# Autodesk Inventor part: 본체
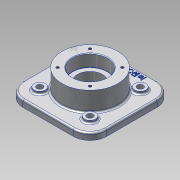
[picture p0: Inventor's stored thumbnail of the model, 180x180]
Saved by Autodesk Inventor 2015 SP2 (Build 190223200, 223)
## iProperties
Created: 2015-07
Part Number: 본체
Material: 일반
Document SubType Name: Modeling
Designer: AMC
Density: 1 g/cm^3
Appearance: 알루미늄 - 평지
Author: AMC
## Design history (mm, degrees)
sketch "스케치1"
  geometry: L1 (-75, -75)-(75, -75); L2 (75, -75)-(75, 75); L3 (75, 75)-(-75, 75); L4 (-75, 75)-(-75, -75); L5 (-75, -75)-(75, 75); L6 (75, -75)-(-75, 75); 1 further point
  constraints: 12 end point, 2 midpoint, 2 parallel, 1 horizontal, 1 perpendicular
  dimensions: "d0" = 150 distance of L3.end L2.end; "d1" = 150 distance of L2.end L1.end
extrude "돌출1" new body sketch "스케치1" distance "d2" = 12; taper "d3" = 0 deg
sketch "스케치2"
  geometry: C1 r 50 at (0, 0); 1 further point
  constraints: 1 centre point, 1 coincident
  dimensions: "d4" = 100 diameter of C1
extrude "돌출2" join sketch "스케치2" distance "d5" = 47; taper "d7" = 0 deg; dims "d6" = 23, "d8" = 0
fillet "모깎기1" dims "d9" = 30
hole "구멍1" diameter "d12" = 45; stored, may be unused: countersink angle "d16" = 90 deg, drill point angle "d18" = 0 deg; dims "d10" = 10, "d11" = 10, "d13" = 6, "d14" = 62, "d15" = 22, "d17" = 8
hole "구멍2" diameter "d21" = 62; stored, may be unused: countersink angle "d25" = 90 deg, drill point angle "d27" = 0 deg; dims "d19" = 10, "d20" = 10, "d22" = 6, "d23" = 62, "d24" = 22, "d26" = 22
sketch "스케치3"
  geometry: C1 r 10 at (-45, 45); C2 r 10 at (45, 45); C3 r 10 at (45, -45); C4 r 10 at (-45, -45); A1 r 30 centre (-45, 45) between (-45, 75) and (-75, 45) reference; A2 r 30 centre (45, 45) between (75, 45) and (45, 75) reference; A3 r 30 centre (45, -45) between (45, -75) and (75, -45) reference; A4 r 30 centre (-45, -45) between (-75, -45) and (-45, -75) reference; 1 further point
  constraints: 4 centre point, 4 coincident
  dimensions: "d28" = 20 diameter of C1; "d29" = 20 diameter of C2; "d30" = 20 diameter of C3; "d31" = 20 diameter of C4
extrude "돌출3" join sketch "스케치3" distance "d32" = 5; taper "d33" = 0 deg
hole "구멍3" diameter "d36" = 11; stored, may be unused: countersink angle "d40" = 90 deg, drill point angle "d42" = 0 deg; dims "d34" = 10, "d35" = 10, "d37" = 6, "d38" = 62, "d39" = 22, "d41" = 22
hole "구멍4" diameter "d45" = 11; stored, may be unused: countersink angle "d49" = 90 deg, drill point angle "d51" = 0 deg; dims "d43" = 10, "d44" = 10, "d46" = 6, "d47" = 62, "d48" = 22, "d50" = 22
hole "구멍5" diameter "d54" = 11; stored, may be unused: countersink angle "d58" = 90 deg, drill point angle "d60" = 0 deg; dims "d52" = 10, "d53" = 10, "d55" = 6, "d56" = 62, "d57" = 22, "d59" = 22
hole "구멍6" diameter "d63" = 11; stored, may be unused: countersink angle "d67" = 90 deg, drill point angle "d69" = 0 deg; dims "d61" = 10, "d62" = 10, "d64" = 6, "d65" = 62, "d66" = 22, "d68" = 22
fillet "모깎기2" dims "d70" = 3
sketch "스케치4"
  geometry: L1 (0, 0)-(41, 0); L2 (0, 0)-(28.991, 28.991); A1 r 41 centre (0, 0) between (41, 0) and (28.991, 28.991); 1 further point
  constraints: 4 end point, 2 point on circle, 1 centre point, 1 coincident, 1 horizontal
  dimensions: "d71" = 82 diameter of A1; "d72" = 45 deg angle of L1 L2
hole "구멍7" sketch "스케치4" at (28.991, 28.991) diameter "d73" = 4.917; stored, may be unused: countersink angle "d77" = 90 deg, drill point angle "d79" = 118 deg; dims "d74" = 10, "d75" = 62, "d76" = 22, "d78" = 13
sketch "스케치5"
  geometry: L1 (0, 0)-(41, 0); L2 (0, 0)-(28.991, 28.991); A1 r 41 centre (0, 0) between (41, 0) and (28.991, 28.991); 1 further point
  constraints: 4 end point, 2 point on circle, 1 centre point, 1 coincident, 1 horizontal
  dimensions: "d83" = 82 diameter of A1; "d84" = 45 deg angle of L1 L2
hole "구멍8" sketch "스케치5" at (28.991, 28.991) diameter "d85" = 4.917; stored, may be unused: countersink angle "d89" = 90 deg, drill point angle "d91" = 118 deg; dims "d86" = 10, "d87" = 62, "d88" = 22, "d90" = 13
fillet "모깎기3" dims "d95" = 0.3
chamfer "모따기1" distance "d96" = 1; stored, may be unused: second distance "d97" = 2, angle "d98" = 45 deg
sketch "스케치6"
  geometry: 2 further points
  constraints: 1 vertical alignment, 1 other
  dimensions: "d99" = 65 distance of point (0, 0) point (0, 65)
feature "엠보싱1" sketch "스케치6" dims "d0" = 150, "d1" = 150, "d100" = 1, "d101" = 0
node "솔리드1"
pattern_circular "원형 패턴1" dims angle "d81" = 360 deg
pattern_circular "원형 패턴2" dims angle "d93" = 360 deg
